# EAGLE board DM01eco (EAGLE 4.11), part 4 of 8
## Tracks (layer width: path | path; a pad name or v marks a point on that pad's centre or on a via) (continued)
DA8-2  (via drill 0.61) (continued)
  Route15 0.152: v267.97,93.98 268.61,93.98 273.05,89.54 v273.05,88.9
DA8-3  (via drill 0.61)
  Top 0.152: v114.94,38.1 117.47,40.64 117.47,52.07 137.16,71.75 139.7,71.75 140.97,73.03 145.41,73.03 v146.05,73.66 | v160.02,62.23 161.93,64.14 161.93,64.77 162.56,65.41 167.64,65.41 185.42,83.19 v185.42,83.82 | v216.53,64.14 217.17,64.14 219.07,66.04 219.07,71.12 241.3,93.34 v245.75,93.34
  Route2 0.152: v245.75,93.34 243.84,95.25 247.65,99.06 247.65,99.7 251.46,103.51 256.54,103.51 259.08,106.05 260.35,106.05 260.99,106.68 262.89,106.68 264.8,104.78 266.06,106.05 273.05,106.05 276.86,109.86 285.75,109.86 291.46,104.14 293.37,104.14 C09.N2
  Route15 0.152: v131.44,15.88 131.44,16.51 117.47,30.48 117.47,35.56 v114.94,38.1 | v185.42,83.82 186.69,83.82 187.96,82.55 198.12,82.55 v216.53,64.14
  Bottom 0.152: v131.44,15.88 128.91,15.88 D22.V2 | v146.05,73.66 149.86,73.66 158.75,64.77 158.75,63.5 v160.02,62.23
DA8-4  (via drill 0.61)
  Top 0.152: v114.3,15.24 102.23,3.18 78.74,3.18 77.47,1.91 75.56,1.91 65.41,12.07 65.41,15.24 D27.V2 | v147.96,1.91 154.31,1.91 154.94,2.54 156.21,2.54 175.26,21.59 175.26,23.5 173.35,25.4 175.26,27.3 v180.97,27.3 | v207.65,2.54 208.28,2.54 222.25,16.51 222.25,17.14 231.14,26.04 231.78,26.04 234.95,29.21 234.95,29.84 v259.71,54.61
  Route2 0.152: v259.71,54.61 259.71,55.88 262.25,58.42 262.89,58.42 276.23,71.75 278.76,71.75 291.46,84.46 291.46,85.73 v297.81,92.08
  Route15 0.152: v114.3,15.24 114.94,14.61 120.02,14.61 121.28,13.34 124.46,13.34 126.36,11.43 128.27,11.43 132.08,7.62 142.24,7.62 v147.96,1.91
  Bottom 0.152: v180.97,27.3 182.25,28.58 207.65,3.18 v207.65,2.54 | v297.81,92.08 295.27,94.62 295.27,96.52 294,97.79 C09.R2
DA8-5  (via drill 0.61)
  Top 0.152: v220.34,116.21 220.34,116.84 226.06,122.56 227.97,122.56 235.59,114.94 v234.95,114.3
  Route2 0.152: v234.95,114.3 236.85,114.3 240.03,111.12 241.3,112.4 243.84,112.4 248.92,107.32 251.46,109.86 259.08,109.86 261.62,107.32 264.16,109.86 272.42,109.86 274.32,107.95 278.76,112.4 v283.85,112.4 | v299.72,100.33 298.45,100.33 296.55,98.43 296.55,97.16 295.27,95.89 295.27,93.98 294,92.71 C09.T2
  Route15 0.152: v220.34,116.21 220.34,116.84 218.44,118.75 213.36,118.75 211.46,120.65 210.82,120.65 196.22,135.25 191.13,135.25 190.5,135.89 189.87,135.89 175.26,150.5 175.26,153.03 151.76,176.53 151.13,176.53 149.86,177.8 149.86,178.44 134.62,193.68 133.99,193.68 132.72,194.94 132.72,195.58 115.57,212.72 115.57,221.62 A23.V2 | v283.85,112.4 283.85,111.76 295.27,100.33 v299.72,100.33
DA8-6  (via drill 0.61)
  Top 0.152: v270.51,118.75 266.7,118.75 v259.08,111.12 | v223.52,125.73 222.88,125.73 221.62,124.46 221.62,121.92 222.88,120.65 218.44,116.21 216.53,116.21 215.9,116.84 215.26,116.21 213.36,116.21 206.38,109.22 v206.38,108.59
  Route2 0.152: v173.99,147.32 170.81,150.5 168.28,147.96 167,147.96 165.1,146.05 161.29,149.86 160.66,149.22 157.48,149.22 156.84,148.59 151.76,148.59 150.5,147.32 149.22,147.32 146.69,144.78 124.46,144.78 119.38,149.86 v118.11,148.59
  Route15 0.152: v270.51,118.75 270.51,118.11 296.55,92.08 294,89.54 294,86.36 C09.V2 | v242.57,126.37 236.22,120.02 234.31,121.92 228.6,121.92 227.97,122.56 227.33,122.56 225.43,124.46 225.43,125.09 224.79,125.73 v223.52,125.73 | v118.11,148.59 116.84,148.59 107.31,158.12 107.31,158.75 100.97,165.1 100.33,165.1 72.39,193.04 71.75,193.04 60.33,204.47 60.33,205.74 54.61,211.46 54.61,212.72 53.98,213.36 53.98,220.34 52.7,221.62 A28.V2
  Bottom 0.152: v259.08,111.12 246.38,123.83 245.11,123.83 v242.57,126.37 | v206.38,108.59 206.38,112.4 199.39,119.38 193.68,119.38 180.97,132.08 180.97,134.62 184.78,138.43 184.15,139.06 184.15,140.34 183.51,140.97 180.34,140.97 v173.99,147.32
DA9  (via drill 0.61)
  Top 0.152: v268.61,233.05 269.24,233.05 276.23,240.03 276.23,240.66 277.5,241.94 278.76,241.94 302.26,265.43 305.44,265.43 306.07,266.06 A08.D2
  Route2 0.152: v268.61,233.05 266.7,231.14 266.7,229.87 250.82,214 250.82,212.72 245.75,207.65 244.47,207.65 234.95,198.12 234.95,197.49 234.31,196.85 234.95,196.22 234.95,193.04 233.04,191.14 228.6,195.58 226.06,195.58 225.43,194.94 219.07,194.94 217.81,193.68 217.81,193.04 215.26,190.5 218.44,187.33 217.81,186.69 217.81,184.78 B15.J2
DA9-0  (via drill 0.61)
  Route2 0.152: v289.56,85.09 295.91,91.44 295.91,92.08 298.45,94.62 298.45,95.89 297.18,97.16 297.81,97.79 v297.81,98.43
  Route15 0.152: v289.56,85.09 292.1,82.55 292.1,76.2 296.55,71.75 298.45,71.75 306.07,64.14 306.07,60.96 D08.D2
  Bottom 0.152: v297.81,98.43 295.27,100.97 295.27,106.05 283.85,117.48 283.21,117.48 281.94,118.75 281.94,122.56 281.31,123.19 C10.F2
DA9-1  (via drill 0.61)
  Top 0.152: v250.82,77.47 250.82,78.11 276.86,104.14 276.86,104.78 278.13,106.05 278.76,106.05 282.57,109.86 v282.57,113.67
  Route2 0.152: v250.82,74.3 247.65,71.12 247.65,69.22 243.21,64.77 243.21,60.96 D13.D2
  Route15 0.152: v250.82,74.3 v250.82,77.47
  Bottom 0.152: v282.57,113.67 282.57,115.57 281.31,116.84 C10.J2
DA9-2  (via drill 0.61)
  Top 0.152: v208.28,29.21 208.91,29.21 v254.63,74.93 | v250.19,79.38 250.19,83.82 257.81,91.44 257.81,92.08 262.25,96.52 262.89,96.52 271.14,104.78 271.78,104.78 276.86,109.86 280.04,109.86 280.67,110.49 C10.L2
  Route15 0.152: v250.19,79.38 v254.63,74.93
  Bottom 0.152: v208.28,29.21 207.65,29.21 196.85,40.01 196.85,40.64 189.23,48.26 188.59,48.26 179.71,57.15 179.71,59.69 D18.D2
DA9-3  (via drill 0.61)
  Top 0.152: v121.28,63.5 118.75,60.96 116.2,60.96 D23.D2 | v189.87,13.34 193.04,13.34 203.2,23.5 208.91,23.5 234.95,49.53 234.95,52.7 v234.31,53.34 | v236.85,58.42 237.49,58.42 247.65,68.58 247.65,69.85 260.35,82.55 261.62,82.55 269.88,90.81 269.88,96.52 276.86,103.51 280.04,103.51 280.67,104.14 C10.N2
  Route2 0.152: v234.31,53.34 234.31,55.88 v236.85,58.42
  Route15 0.152: v121.28,63.5 122.56,63.5 152.4,33.66 153.03,33.66 156.21,30.48 161.93,30.48 165.1,27.3 170.81,27.3 182.25,15.88 182.25,15.24 183.51,13.97 189.23,13.97 v189.87,13.34
DA9-4  (via drill 0.61)
  Route2 0.152: v71.12,78.11 64.14,71.12 64.14,69.22 55.88,60.96 52.7,60.96 D28.D2 | v154.31,10.79 158.12,10.79 174.62,27.3 175.9,27.3 178.44,29.84 184.15,29.84 190.5,36.2 196.22,36.2 200.66,40.64 200.66,41.27 201.93,42.55 206.38,42.55 210.82,38.1 212.72,40.01 219.71,40.01 228.6,48.89 v231.78,48.89 | v241.3,41.91 241.3,43.81 241.94,44.45 241.94,45.72 240.03,47.62 251.46,59.05 256.54,59.05 257.18,59.69 257.18,65.41 282.57,90.81 282.57,94.62 280.04,97.16 280.67,97.79 C10.R2
  Route15 0.152: v133.35,12.07 153.03,12.07 v154.31,10.79
  Bottom 0.152: v71.12,78.11 71.12,76.84 93.98,53.98 93.98,52.7 95.25,51.43 95.25,48.89 93.98,47.62 104.78,36.83 110.49,36.83 127.64,19.69 127.64,17.14 126.36,15.88 129.54,12.7 132.72,12.7 v133.35,12.07 | v231.78,48.89 232.41,48.89 236.22,45.09 236.22,44.45 239.4,41.27 240.66,41.27 v241.3,41.91
DA9-5  (via drill 0.61)
  Top 0.152: v265.43,81.28 267.33,81.28 276.86,90.81 280.04,90.81 280.67,91.44 C10.T2
  Route2 0.152: v175.9,179.07 175.9,177.8 171.45,173.36 171.45,172.09 170.81,171.45 170.81,169.55 172.72,167.64 168.28,163.19 v168.28,153.03 | v219.07,100.97 219.07,99.06 224.16,93.98 224.79,93.98 229.87,88.9 227.97,87 v227.33,87 | v244.47,69.85 244.47,70.48 245.11,71.12 246.38,71.12 250.82,75.57 253.37,75.57 260.35,82.55 261.62,82.55 262.89,83.82 264.16,83.82 266.06,81.92 v265.43,81.28
  Route15 0.152: v175.9,179.07 175.26,179.07 168.28,186.06 168.28,191.77 157.48,202.56 158.75,203.84 158.75,207.01 158.12,207.65 158.12,209.55 149.86,217.81 149.86,222.89 106.68,266.06 103.5,266.06 A24.D2 | v168.28,153.03 168.28,150.5 187.96,130.81 189.23,130.81 196.85,123.19 196.85,122.56 213.36,106.05 218.44,106.05 222.25,102.23 222.25,100.33 220.98,99.06 v219.07,100.97
  Bottom 0.152: v227.33,87 227.33,86.36 243.84,69.85 v244.47,69.85
DA9-6  (via drill 0.61)
  Top 0.152: v223.52,140.34 226.69,137.16 227.33,137.8 227.97,137.8 229.24,139.06 229.24,140.34 228.6,140.97 v248.92,161.29 | v304.17,104.78 306.7,102.23 298.45,93.98 297.81,93.98 294.64,90.81 288.93,90.81 285.75,87.63 283.85,87.63 281.31,85.09 C10.V2
  Route2 0.152: v210.19,180.97 210.19,180.34 v200.66,170.81
  Route15 0.152: v210.19,180.97 203.2,187.96 203.2,189.23 193.68,198.75 193.68,204.47 161.29,236.86 160.66,236.86 154.94,242.57 149.22,242.57 144.78,247.02 144.78,247.65 101.6,290.83 67.31,290.83 43.81,267.33 40.01,267.33 A29.D2 | v248.92,161.29 249.56,161.29 257.18,153.67 257.18,150.5 271.14,136.53 271.14,135.89 272.42,134.62 273.69,134.62 279.4,128.91 280.04,128.91 281.31,127.64 281.31,127 288.93,119.38 288.93,118.11 290.83,116.21 292.1,116.21 303.53,104.78 v304.17,104.78
  Bottom 0.152: v200.66,170.81 198.12,168.28 213.36,153.03 213.36,150.5 v223.52,140.34
DA10  (via drill 0.61)
  Top 0.152: v271.78,223.52 274.95,226.69 275.59,226.69 307.98,259.08 307.98,261.62 309.25,262.89 A08.E2
  Route2 0.152: v271.78,223.52 271.78,222.89 267.33,218.44 267.33,211.46 263.52,207.65 257.81,207.65 252.73,202.56 251.46,202.56 237.49,188.59 231.78,188.59 221.62,178.44 217.81,178.44 B15.L2
DA10-0  (via drill 0.61)
  Top 0.152: v254.63,107.95 259.08,112.4 259.71,112.4 267.33,120.02 267.33,122.56 267.97,123.19 C11.F2
  Bottom 0.152: v254.63,107.95 259.08,103.51 259.71,103.51 305.44,57.78 309.25,57.78 D08.E2
DA10-1  (via drill 0.61)
  Top 0.152: v233.04,73.03 257.81,97.79 257.81,98.43 260.99,101.6 261.62,101.6 269.88,109.86 v269.88,114.94
  Bottom 0.152: v233.04,73.03 245.75,60.32 245.75,57.78 D13.E2 | v269.88,114.94 269.88,115.57 268.61,116.84 C11.J2
DA10-2  (via drill 0.61)
  Top 0.152: v215.9,83.82 214.63,82.55 209.55,82.55 196.85,69.85 196.85,68.58 189.87,61.59 189.23,61.59 187.32,59.69 187.32,59.05 186.06,57.78 182.88,57.78 D18.E2 | v259.08,104.78 264.16,109.86 267.33,109.86 267.97,110.49 C11.L2
  Route2 0.152: v224.79,75.57 229.24,75.57 238.76,85.09 238.76,85.73 240.03,87 240.66,87 251.46,97.79 251.46,98.43 252.73,99.7 254,99.7 v259.08,104.78
  Route15 0.152: v215.9,83.82 216.53,83.82 v224.79,75.57
DA10-3  (via drill 0.61)
  Top 0.152: v158.75,24.13 159.38,24.13 175.26,40.01 181.61,40.01 184.78,43.18 187.32,43.18 189.23,41.27 v190.5,42.55 | v259.08,98.43 264.16,103.51 267.33,103.51 267.97,104.14 C11.N2
  Route2 0.152: v190.5,42.55 196.22,42.55 226.69,73.03 231.78,73.03 233.04,74.3 234.31,74.3 258.44,98.43 v259.08,98.43
  Route15 0.152: v158.75,24.13 156.21,24.13 150.5,29.84 149.22,29.84 122.56,56.52 119.38,56.52 D23.E2
DA10-4  (via drill 0.61)
  Top 0.152: v115.57,2.54 118.11,2.54 v129.54,13.97 | v144.78,1.91 151.13,8.26 151.76,8.26 153.03,6.99 152.4,6.35 154.31,4.45 160.02,10.16 v160.02,10.79
  Route2 0.152: v160.02,10.79 188.59,10.79 190.5,12.7 203.2,12.7 204.47,13.97 206.38,13.97 222.25,29.84 222.25,30.48 253.37,61.59 254.63,61.59 256.54,63.5 256.54,65.41 266.06,74.93 266.06,76.2 266.7,76.84 266.7,88.27 269.88,91.44 269.88,96.52 268.61,97.79 C11.R2
  Bottom 0.152: v115.57,2.54 103.5,14.61 101.6,14.61 69.85,46.35 63.5,46.35 55.88,53.98 55.88,56.52 D28.E2 | v129.54,13.97 132.72,13.97 v144.78,1.91
DA10-5  (via drill 0.61)
  Top 0.152: v122.56,144.78 122.56,149.22 149.22,175.9 149.22,177.16 151.13,179.07 152.4,179.07 v158.75,185.42 | v100.33,259.08 100.33,259.71 102.23,261.62 104.78,261.62 106.05,262.89 A24.E2
  Route2 0.152: v214.63,46.35 215.26,46.35 215.9,46.99 219.71,43.18 221.62,43.18 222.88,44.45 221.62,45.72 221.62,48.26 245.11,71.75 246.38,71.75 259.71,85.09 259.71,86.36 264.8,91.44 267.97,91.44 C11.T2 | v141.6,113.67 141.6,115.57 146.05,120.02 v146.05,120.65
  Route15 0.152: v158.75,185.42 158.75,187.96 154.94,191.77 154.94,193.04 142.88,205.11 142.88,209.55 139.7,212.72 139.7,220.34 100.97,259.08 v100.33,259.08
  Bottom 0.152: v214.63,46.35 214.63,46.99 196.85,64.77 190.5,64.77 165.74,89.54 165.74,90.17 152.4,103.51 151.76,103.51 v141.6,113.67 | v146.05,120.65 146.05,121.29 145.41,121.92 140.34,121.92 130.18,132.08 130.18,137.8 123.19,144.78 v122.56,144.78
DA10-6  (via drill 0.61)
  Top 0.152: v156.84,204.47 156.84,203.84 v154.31,201.3 | v243.21,94.62 245.11,96.52 v248.92,96.52 | v264.16,82.55 265.43,82.55 267.97,85.09 C11.V2
  Route15 0.152: v156.84,204.47 155.57,205.74 155.57,210.82 139.06,227.33 139.06,228.6 137.79,229.87 136.53,229.87 110.49,255.91 105.41,255.91 104.78,256.54 104.78,261.62 87.63,278.76 81.92,278.76 71.75,288.92 46.99,264.16 43.18,264.16 A29.E2 | v154.31,201.3 153.03,200.03 158.75,194.31 158.75,191.14 157.48,189.87 169.54,177.8 169.54,177.16 173.35,173.36 173.99,173.36 179.71,167.64 179.71,167 180.97,165.74 180.97,160.66 190.5,151.13 194.31,151.13 203.84,141.61 203.84,139.7 209.55,133.98 209.55,131.44 208.28,130.18 213.36,125.09 214.63,125.09 215.9,123.83 215.9,121.92 v243.21,94.62
  Bottom 0.152: v248.92,96.52 248.92,95.89 260.99,83.82 262.89,83.82 v264.16,82.55
DA11  (via drill 0.61)
  Top 0.152: v217.17,167 217.17,170.81 B15.N2 | v255.91,188.59 256.54,188.59 267.33,199.39 267.33,201.93 266.06,203.2 282.57,219.71 283.21,219.71 284.48,220.98 284.48,222.89 295.27,233.68 295.27,239.4 304.8,248.92 304.8,250.19 307.98,253.37 307.98,255.27 309.25,256.54 A08.H2
  Route2 0.152: v223.52,160.66 225.43,160.66 227.33,158.75 254,185.42 254,186.69 v255.91,188.59
  Route15 0.152: v217.17,167 217.81,167 223.52,161.29 v223.52,160.66
DA11-0  (via drill 0.61)
  Top 0.152: v259.71,117.48 259.71,115.57 260.99,114.3 259.71,113.03 255.27,113.03 v253.37,111.12 | v298.45,57.15 300.36,57.15 304.17,53.34 v304.8,53.98
  Route15 0.152: v253.37,111.12 253.37,110.49 255.91,107.95 255.91,106.68 257.18,105.41 257.18,104.78 259.08,102.87 259.71,102.87 260.35,102.23 260.35,100.97 257.81,98.43 262.25,93.98 262.89,93.98 269.88,87 269.88,81.28 289.56,61.59 294.64,61.59 298.45,57.78 v298.45,57.15 | v304.8,53.98 304.8,53.34 305.44,52.7 307.98,52.7 309.25,51.43 D08.H2
  Bottom 0.152: v259.71,117.48 255.91,121.29 255.91,123.19 C12.F2
DA11-1  (via drill 0.61)
  Top 0.152: v230.5,69.22 247.65,86.36 247.65,87 251.46,90.81 v252.09,90.81 | v241.94,102.23 243.21,102.23 254.63,113.67 254.63,116.21 255.27,116.84 C12.J2
  Bottom 0.152: v230.5,69.22 245.75,53.98 245.75,51.43 D13.H2 | v252.09,90.81 252.09,92.08 v241.94,102.23
DA11-2  (via drill 0.61)
  Top 0.152: v189.23,46.99 189.23,47.62 201.29,59.69 201.93,59.69 207.01,64.77 212.09,64.77 247.65,100.33 247.65,103.51 246.38,104.78 251.46,109.86 254.63,109.86 255.27,110.49 C12.L2
  Route15 0.152: v189.23,46.99 186.06,50.16 182.88,50.16 D18.H2
DA11-3  (via drill 0.61)
  Top 0.152: v153.67,6.35 175.26,27.94 176.53,27.94 178.44,29.84 184.15,29.84 205.74,51.43 v206.38,51.43 | v227.33,71.75 230.5,71.75 243.21,84.46 243.84,84.46 247.65,88.27 247.65,90.81 246.38,92.08 251.46,97.16 252.73,97.16 254,98.43 254,99.06 256.54,101.6 v257.18,101.6
  Route2 0.152: v114.94,43.81 118.75,47.62 118.75,50.16 D23.H2 | v206.38,51.43 206.38,52.07 226.06,71.75 v227.33,71.75
  Bottom 0.152: v114.94,43.81 115.57,43.81 120.02,39.37 121.28,39.37 130.81,29.84 130.81,29.21 v153.67,6.35 | v257.18,101.6 257.18,102.87 255.91,104.14 C12.N2
DA11-4  (via drill 0.61)
  Top 0.152: v109.86,4.45 110.49,4.45 115.57,9.53 119.38,9.53 152.4,42.55 157.48,42.55 158.75,43.81 v158.75,44.45 | v201.93,3.81 248.28,50.16 248.28,50.8 249.56,52.07 250.19,52.07 254.63,56.52 254.63,58.42 253.37,59.69 v254,60.32
  Route2 0.152: v254,66.04 253.37,66.67 256.54,69.85 256.54,76.84 v257.18,77.47 | v253.37,82.55 254.63,82.55 257.81,85.73 257.81,87.63 253.37,92.08 v257.18,95.89
  Route15 0.152: v176.53,23.5 180.97,23.5 190.5,13.97 191.77,13.97 v201.93,3.81
  Bottom 0.152: v109.86,4.45 103.5,10.79 97.79,10.79 91.44,17.14 86.36,17.14 85.72,17.78 79.38,17.78 55.88,41.27 57.15,42.55 57.15,45.09 55.88,46.35 55.88,50.16 D28.H2 | v158.75,44.45 160.02,44.45 165.74,38.73 165.74,36.2 164.47,34.92 171.45,27.94 171.45,27.3 175.26,23.5 v176.53,23.5 | v254,60.32 254,60.96 256.54,63.5 v254,66.04 | v257.18,77.47 257.18,78.74 v253.37,82.55 | v257.18,95.89 257.18,96.52 255.91,97.79 C12.R2
DA11-5  (via drill 0.61)
  Route2 0.152: v257.81,99.7 260.35,99.7 260.99,100.33 262.89,100.33 264.8,98.43 260.35,93.98 257.18,93.98 255.91,92.71 C12.T2
  Route15 0.152: v229.87,128.27 227.33,130.81 226.69,130.81 210.82,146.69 208.91,146.69 207.01,148.59 207.01,149.86 206.38,150.5 206.38,153.67 193.68,166.37 193.68,179.07 165.74,207.01 165.74,220.34 109.86,276.22 101.6,267.97 101.6,266.06 106.05,261.62 106.05,257.81 A24.H2 | v245.75,111.76 245.75,111.12 257.18,99.7 v257.81,99.7
  Bottom 0.152: v229.87,128.27 229.87,127 238.76,118.11 238.76,117.48 240.03,116.21 241.3,116.21 v245.75,111.76
DA11-6  (via drill 0.61)
  Top 0.152: v233.68,99.7 234.31,99.7 238.76,104.14 238.76,104.78 240.03,106.05 240.66,106.05 241.94,107.32 241.94,108.59 243.21,109.86 245.11,109.86 v247.01,111.76 | v226.06,149.22 224.79,150.5 220.98,150.5 219.71,149.22 218.44,149.22 215.26,152.4 v219.07,156.21 | v81.92,280.03 73.03,280.03 72.39,279.4 67.94,279.4 62.87,274.32 60.96,274.32 59.05,276.22 43.81,260.99 43.81,258.44 43.18,257.81 A29.H2
  Route2 0.152: v248.28,81.92 251.46,85.09 255.27,85.09 C12.V2
  Route15 0.152: v219.07,156.21 217.81,156.21 214,160.02 213.36,160.02 208.91,164.47 208.91,166.37 210.82,168.28 202.56,176.53 200.66,176.53 198.75,174.62 170.81,202.56 170.81,205.11 172.09,206.38 171.45,207.01 171.45,217.81 170.18,219.08 170.18,221.62 161.29,230.5 156.21,230.5 152.4,234.31 v152.4,234.95 | v146.05,244.47 146.05,245.11 139.7,251.46 139.7,252.09 113.67,278.13 88.9,278.13 87.63,279.4 82.55,279.4 v81.92,280.03
  Bottom 0.152: v248.28,81.92 248.28,83.19 235.59,95.89 234.95,95.89 233.68,97.16 v233.68,99.7 | v247.01,111.76 249.56,114.3 246.38,117.48 246.38,118.11 245.11,119.38 243.84,119.38 238.12,125.09 238.12,126.37 237.49,127 237.49,128.27 242.57,133.35 240.66,135.25 238.76,135.25 236.85,133.35 233.04,137.16 234.95,139.06 234.95,140.97 228.6,147.32 227.97,147.32 v226.06,149.22 | v152.4,234.95 151.13,234.95 145.41,240.66 145.41,242.57 146.69,243.84 v146.05,244.47
DA_SEL_DEV0  (via drill 0.61)
  Top 0.152: v214.63,123.83 215.26,123.83 216.53,125.09 219.07,125.09 220.34,126.37 C15.E2 | C13.E2 245.75,126.37 244.47,125.09 241.94,125.09 240.03,123.19 236.85,126.37 233.68,126.37 C14.E2 233.04,126.37 231.78,125.09 229.24,125.09 227.97,123.83 v227.33,123.83 | v366.39,125.09 370.84,125.09 372.75,127 C03.E2 | 297.18,127.64 300.99,127.64 302.26,128.91 307.98,128.91 309.25,127.64 C08.E2 309.88,126.37 313.06,126.37 316.23,123.19 318.13,125.09 320.68,125.09 321.94,126.37 C07.E2 | 297.18,127.64 C09.E2 297.18,127.64 | v344.17,120.02 347.35,123.19 347.35,126.37 C05.E2 | v354.33,123.19 357.5,126.37 360.05,126.37 C04.E2 | 297.18,127.64 298.45,128.91 296.55,130.81 294.64,128.91 289.56,128.91 288.93,128.27 285.75,128.27 285.12,127.64 284.48,127.64 C10.E2 | v401.32,133.98 401.32,132.72 399.42,130.81 399.42,128.27 398.78,127.64 C01.E2 398.14,126.37 396.88,125.09 v390.52,125.09 | v291.46,221.62 293.37,219.71 297.81,224.16 298.45,224.16 v305.44,231.14 | v381,124.46 381.63,125.09 384.18,125.09 385.44,126.37 C02.E2
  Route2 0.152: v227.33,123.83 224.16,127 220.98,127 C15.E2 | C11.E2 271.78,127.64 273.69,127.64 278.13,123.19 280.04,125.09 282.57,125.09 283.85,126.37 C10.E2 | C13.E2 246.38,127.64 250.19,127.64 251.46,128.91 257.18,128.91 258.44,127.64 C12.E2
  Route15 0.152: v246.38,267.33 243.21,267.33 A13.D2 | v323.21,213.36 325.12,213.36 330.83,207.65 330.83,207.01 339.73,198.12 343.54,198.12 344.17,197.49 B05.D2 | v390.52,125.09 389.25,126.37 386.08,126.37 C02.E2
  Bottom 0.152: v214.63,123.83 211.46,127 208.28,127 C16.E2 | C12.E2 259.08,127.64 262.25,127.64 267.97,133.35 271.14,130.18 271.78,130.18 276.86,125.09 279.4,125.09 282.57,128.27 283.85,127 C10.E2 | v366.39,125.09 365.76,125.09 364.49,126.37 360.68,126.37 C04.E2 | C07.E2 322.58,127.64 325.75,127.64 328.93,130.81 330.83,128.91 333.38,128.91 334.64,127.64 C06.E2 335.28,126.37 335.92,125.73 335.92,123.19 341.63,117.48 v344.17,120.02 | v354.33,123.19 351.79,125.73 348.62,125.73 347.98,126.37 C05.E2 | v401.32,133.98 384.81,150.5 387.35,153.03 387.35,156.21 383.54,160.02 378.46,160.02 377.82,160.66 376.56,160.66 370.84,166.37 370.84,167 344.81,193.04 344.81,196.22 B05.D2 | v246.38,267.33 246.38,266.7 v291.46,221.62 | v305.44,231.14 306.7,231.14 314.96,222.89 314.96,221.62 v323.21,213.36 | v381,124.46 378.46,124.46 377.19,125.73 375.92,125.73 375.29,126.37 373.38,126.37 C03.E2
DA_SEL_DEV1  (via drill 0.61)
  Top 0.152: v214.63,117.48 215.26,117.48 216.53,118.75 219.07,118.75 220.34,120.02 C15.H2 | C14.H2 233.68,121.29 237.49,121.29 238.76,122.56 244.47,122.56 245.75,121.29 C13.H2 | v290.83,117.48 293.37,120.02 296.55,120.02 C09.H2 | v367.03,117.48 367.67,117.48 368.94,118.75 371.48,118.75 372.75,120.02 C03.H2 | v331.47,174.62 344.17,187.33 344.17,189.87 B05.F2 | v353.06,149.86 353.06,148.59 334.01,129.54 | 334.01,129.54 326.39,121.92 323.21,121.92 322.58,121.29 C07.H2 321.94,121.29 320.04,119.38 316.87,122.56 314.96,122.56 311.15,118.75 311.15,118.11 310.51,117.48 311.15,116.84 311.15,113.67 309.25,111.76 307.98,113.03 307.98,114.94 309.25,116.21 309.25,120.02 C08.H2 | 334.01,129.54 v333.38,130.18 | v360.05,116.21 360.05,120.02 C04.H2
  Route2 0.152: C12.H2 258.44,121.29 255.27,121.29 252.73,123.83 250.19,121.29 246.38,121.29 C13.H2 | C15.H2 220.98,121.29 224.79,121.29 226.06,122.56 227.97,122.56 231.14,119.38 233.04,121.29 C14.H2 | v379.73,117.48 381,118.75 382.9,118.75 384.18,120.02 385.44,120.02 C02.H2 | C07.H2 322.58,120.02 325.75,120.02 328.93,116.84 330.83,118.75 333.38,118.75 334.64,120.02 C06.H2
  Route15 0.152: v214.63,117.48 214,117.48 211.46,120.02 208.28,120.02 C16.H2 | v387.35,122.56 386.08,121.29 C02.H2 | v259.08,123.83 259.08,121.29 C12.H2
  Bottom 0.152: C09.H2 297.18,120.02 300.99,120.02 302.26,118.75 308.61,118.75 309.88,120.02 C08.H2 | 269.88,127.64 269.88,126.37 271.14,125.09 271.14,121.29 C11.H2 | 269.88,127.64 271.78,129.54 276.86,124.46 279.4,124.46 280.67,125.73 281.31,125.09 281.94,125.09 282.57,124.46 282.57,122.56 283.85,121.29 C10.H2 284.48,120.02 285.12,119.38 288.29,119.38 290.19,117.48 v290.83,117.48 | v387.35,122.56 391.16,118.75 396.88,118.75 398.14,120.02 C01.H2 | v367.03,117.48 364.49,120.02 360.68,120.02 C04.H2 | v379.73,117.48 379.1,117.48 377.19,119.38 374.01,119.38 373.38,120.02 C03.H2 | v353.06,149.86 353.06,153.03 v331.47,174.62 307.98,198.12 302.26,198.12 298.45,201.93 298.45,202.56 278.76,222.25 280.04,223.52 280.04,226.06 275.59,230.5 269.88,230.5 260.35,240.03 260.35,240.66 258.44,242.57 257.81,242.57 243.21,257.18 243.21,259.71 A13.F2 | 347.35,121.92 347.35,123.19 345.44,125.09 339.73,125.09 336.55,128.27 335.28,128.27 v333.38,130.18 | 347.35,121.92 347.35,121.29 C05.H2 | v360.05,116.21 355.6,116.21 351.79,120.02 351.79,120.65 350.52,121.92 347.35,121.92 | v259.08,123.83 265.43,130.18 266.7,128.91 268.61,128.91 269.88,127.64
DA_SEL_DEV2  (via drill 0.61)
  Top 0.152: C14.K2 233.04,114.94 233.04,116.84 229.87,120.02 225.43,115.57 221.62,115.57 220.98,114.94 C15.K2 | 257.81,117.48 259.08,116.21 259.08,114.94 C12.K2 | 257.81,117.48 256.54,118.75 254,118.75 250.19,114.94 246.38,114.94 C13.K2 | v260.35,122.56 260.35,120.02 257.81,117.48 | v371.48,112.4 372.75,113.67 C03.K2 | v394.97,113.03 396.24,113.03 396.88,112.4 398.14,113.67 C01.K2 | v379.73,109.86 379.73,110.49 381.63,112.4 384.18,112.4 385.44,113.67 C02.K2 | 311.15,121.29 311.15,120.02 309.88,118.75 309.88,114.94 C08.K2 | 311.15,121.29 308.61,123.83 307.34,122.56 302.26,122.56 297.81,118.11 297.81,115.57 297.18,114.94 C09.K2 | v329.56,110.49 329.56,111.12 330.83,112.4 333.38,112.4 334.64,113.67 C06.K2 | v366.39,160.02 366.39,158.75 358.77,151.13 356.24,151.13 323.21,118.11 323.21,115.57 322.58,114.94 C07.K2 | v262.25,269.88 252.09,259.71 251.46,259.71 246.38,254.64 243.21,254.64 A13.J2 | 311.15,121.29 311.79,121.29 v312.42,121.92 | v351.15,109.22 351.79,109.22 356.24,113.67 360.05,113.67 C04.K2
  Route2 0.152: C16.K2 208.28,114.94 208.28,117.48 210.19,119.38 212.72,119.38 214,118.11 214.63,118.75 219.07,118.75 221.62,116.21 220.34,114.94 C15.K2 | C09.K2 296.55,114.94 295.27,116.21 289.56,116.21 288.29,114.94 284.48,114.94 C10.K2 283.85,114.94 282.57,116.21 276.86,116.21 275.59,114.94 271.78,114.94 C11.K2
  Route15 0.152: C14.K2 233.68,114.94 233.68,118.11 235.59,120.02 236.22,119.38 238.12,119.38 238.76,118.75 240.03,118.75 241.3,117.48 241.3,116.84 241.94,116.21 244.47,116.21 245.75,114.94 C13.K2 | C06.K2 335.28,113.67 335.92,113.03 339.09,113.03 341.63,110.49 344.81,113.67 347.35,113.67 C05.K2 347.98,113.67 347.98,109.86 349.88,107.95 v351.15,109.22
  Bottom 0.152: v260.35,122.56 269.24,113.67 271.14,113.67 C11.K2 | v371.48,112.4 365.76,112.4 363.86,114.3 363.22,113.67 360.68,113.67 C04.K2 | v394.97,113.03 393.06,111.12 391.8,111.12 389.25,113.67 386.08,113.67 C02.K2 | v379.73,109.86 379.1,110.49 377.82,109.22 375.29,109.22 373.38,111.12 373.38,113.67 C03.K2 | v329.56,110.49 327.02,113.03 323.85,113.03 323.21,113.67 322.58,113.67 C07.K2 321.94,114.94 320.68,116.21 317.5,116.21 312.42,121.29 v312.42,121.92 | 344.81,182.25 344.81,181.61 349.25,177.16 349.25,176.53 365.76,160.02 v366.39,160.02 | 344.81,182.25 344.81,183.52 B05.J2 | v262.25,269.88 295.27,236.86 301.62,236.86 316.87,221.62 316.87,220.98 333.38,204.47 333.38,198.75 347.35,184.78 347.98,184.78 349.25,183.52 347.98,182.25 344.81,182.25
DA_SEL_DEV3  (via drill 0.61)
  Top 0.152: v228.6,104.78 228.6,105.41 230.5,107.32 233.04,107.32 C14.M2 | v240.03,104.78 242.57,107.32 245.75,107.32 C13.M2 | v278.13,104.78 278.76,104.78 280.04,106.05 282.57,106.05 | 282.57,106.05 283.85,107.32 C10.M2 | 293.37,113.67 296.55,110.49 296.55,108.59 C09.M2 | 293.37,113.67 282.57,102.87 282.57,101.6 280.67,99.7 279.4,100.97 282.57,104.14 282.57,106.05 | v379.73,104.14 381.63,106.05 384.18,106.05 385.44,107.32 C02.M2 | v388.62,106.68 389.25,107.32 390.52,106.05 393.06,106.05 394.33,107.32 398.14,107.32 C01.M2 | v325.12,109.22 324.49,109.22 322.58,107.32 C07.M2 | v371.48,147.96 371.48,141.61 v350.52,120.65 v343.54,113.67 339.09,109.22 335.92,109.22 335.28,108.59 C06.M2 | v252.09,254 250.19,252.09 245.11,252.09 243.21,250.19 243.21,248.28 A13.L2 | 293.37,113.67 293.37,114.94 296.55,118.11 v296.55,118.75 | v261.62,109.22 260.99,108.59 259.08,108.59 C12.M2
  Route2 0.152: C13.M2 246.38,107.32 246.38,104.14 248.92,101.6 251.46,104.14 252.73,104.14 254.63,106.05 257.18,106.05 258.44,107.32 C12.M2 | v210.82,115.57 210.82,114.94 207.65,111.76 207.65,108.59 C16.M2 | C08.M2 309.88,108.59 313.06,108.59 314.96,110.49 316.23,110.49 318.13,112.4 320.04,112.4 323.21,109.22 322.58,108.59 C07.M2 | v367.03,103.51 367.03,104.14 370.2,107.32 372.75,107.32 C03.M2 | v261.62,109.22 262.89,109.22 264.16,110.49 265.43,110.49 v266.06,111.12
  Route15 0.152: v210.82,115.57 210.82,114.94 213.36,112.4 218.44,112.4 219.07,111.76 219.07,109.86 220.34,108.59 C15.M2 | v240.03,104.78 239.4,104.78 237.49,106.68 234.31,106.68 233.68,107.32 C14.M2
  Bottom 0.152: v228.6,104.78 227.33,104.78 224.79,107.32 220.98,107.32 C15.M2 | v278.13,104.78 275.59,107.32 271.78,107.32 C11.M2 271.14,108.59 269.88,109.86 267.33,109.86 v266.06,111.12 | v379.73,104.14 376.56,107.32 373.38,107.32 C03.M2 | v388.62,106.68 386.71,106.68 386.08,107.32 C02.M2 | v325.12,109.22 325.12,108.59 327.66,106.05 328.93,106.05 329.56,105.41 331.47,107.32 334.64,107.32 C06.M2 | 344.81,174.62 344.81,177.16 B05.L2 | v371.48,147.96 344.81,174.62 | v343.54,113.67 344.17,113.67 347.35,110.49 347.35,108.59 C05.M2 | 360.05,111.12 360.05,108.59 C04.M2 | v350.52,120.65 360.05,111.12 | v252.09,254 252.73,254 266.06,240.66 266.7,240.66 273.05,234.31 273.05,233.68 286.38,220.34 290.83,220.34 293.37,217.81 297.18,221.62 314.32,204.47 320.04,204.47 320.68,203.84 320.68,201.3 319.4,200.03 344.81,174.62 | v367.03,103.51 367.03,104.14 360.05,111.12 | v296.55,118.75 296.55,118.11 306.07,108.59 309.25,108.59 C08.M2
DA_SEL_DEV4  (via drill 0.61)
  Top 0.152: v231.78,247.02 232.41,247.02 250.82,265.43 v254,265.43 | v328.93,104.78 325.75,101.6 322.58,101.6 C07.P2 321.94,100.97 321.94,99.06 v320.68,97.79 | v387.99,100.33 391.16,103.51 396.88,103.51 398.14,102.23 C01.P2 | v354.33,98.43 355.6,99.7 358.77,99.7 360.05,100.97 C04.P2 | 369.57,100.97 372.75,100.97 C03.P2 | v367.03,98.43 369.57,100.97 | v379.1,106.05 378.46,106.05 376.56,107.95 369.57,100.97 | C06.P2 335.28,102.23 335.28,104.78 342.9,112.4 343.54,112.4 346.71,115.57 v350.52,115.57 351.79,115.57 355.6,119.38 355.6,120.02 362.58,127 361.31,128.27 361.31,130.81 370.2,139.7 v370.84,139.7 | v214.63,98.43 215.26,98.43 216.53,99.7 219.07,99.7 220.34,100.97 C15.P2 | v231.78,93.98 234.95,93.98 241.94,100.97 245.75,100.97 C13.P2 | v274.32,102.87 272.42,102.87 271.78,102.23 C11.P2 | v287.02,93.98 287.02,94.62 292.1,99.7 295.27,99.7 296.55,100.97 C09.P2 | v241.3,104.78 241.3,105.41 241.94,106.05 246.38,106.05 248.92,108.59 v248.92,109.22
  Route2 0.152: v343.54,205.74 343.54,205.11 339.73,201.3 339.73,200.66 337.82,198.75 337.19,198.75 333.38,194.94 v333.38,184.15 | v387.99,100.33 387.35,99.7 386.08,100.97 C02.P2 | C12.P2 259.08,101.6 262.25,101.6 264.16,103.51 269.88,103.51 271.14,102.23 C11.P2 | v241.3,104.78 240.03,103.51 238.76,103.51 237.49,102.23 233.68,102.23 C14.P2 | v320.68,97.79 320.04,97.16 316.87,97.16 313.06,100.97 v312.42,100.33
  Route15 0.152: v254,265.43 260.35,265.43 264.16,261.62 269.88,261.62 300.36,231.14 300.99,231.14 302.26,229.87 311.15,229.87 313.06,231.78 314.96,229.87 320.68,229.87 343.54,207.01 v343.54,205.74 | v333.38,184.15 333.38,179.71 340.36,172.72 343.54,172.72 344.17,172.09 B05.N2 344.81,170.81 344.81,167.64 360.05,152.4 360.05,151.13 370.84,140.34 v370.84,139.7 | v379.1,106.05 382.9,102.23 385.44,102.23 C02.P2 | v214.63,98.43 214,98.43 211.46,100.97 208.28,100.97 C16.P2
  Bottom 0.152: v231.78,247.02 233.04,245.75 234.31,245.75 236.85,243.21 237.49,243.21 238.76,241.94 242.57,241.94 A13.N2 | v328.93,104.78 329.56,104.78 330.83,103.51 333.38,103.51 334.64,102.23 C06.P2 | v354.33,98.43 351.79,100.97 347.98,100.97 C05.P2 | C04.P2 360.68,100.97 361.31,100.33 364.49,100.33 366.39,98.43 v367.03,98.43 350.52,114.94 v350.52,115.57 | 223.52,100.97 222.88,100.33 220.98,102.23 C15.P2 | 223.52,100.97 226.06,103.51 227.97,103.51 229.24,102.23 233.04,102.23 C14.P2 | v231.78,93.98 228.6,97.16 227.97,97.16 224.16,100.97 223.52,100.97 | 274.95,102.23 276.23,103.51 278.76,103.51 280.04,102.23 283.85,102.23 C10.P2 | 274.95,102.23 v274.32,102.87 | C09.P2 296.55,102.23 296.55,106.05 295.27,107.32 295.27,113.03 294,114.3 296.55,116.84 298.45,114.94 298.45,112.4 297.18,111.12 302.26,106.05 307.34,106.05 307.98,105.41 307.98,103.51 309.25,102.23 C08.P2 309.88,100.97 310.51,100.33 v312.42,100.33 | 274.95,102.23 274.95,101.6 282.57,93.98 v287.02,93.98 | v248.92,109.22 248.92,108.59 257.18,100.33 258.44,101.6 C12.P2
DA_SEL_DEV5  (via drill 0.61)
  Top 0.152: v337.82,96.52 337.19,95.89 335.28,95.89 C06.S2 | v379.1,99.7 378.46,99.06 377.19,100.33 375.29,100.33 373.38,98.43 373.38,95.89 C03.S2 | v234.95,97.16 233.68,95.89 C14.S2 | v204.47,199.39 204.47,200.03 207.65,203.2 208.28,203.2 239.4,234.31 242.57,234.31 A13.R2 | v279.4,98.43 277.5,98.43 275.59,96.52 272.42,96.52 271.78,95.89 C11.S2 | v290.83,92.08 293.37,94.62 296.55,94.62 C09.S2 297.18,95.89 v298.45,97.16 | v285.75,97.16 284.48,95.89 C10.S2 | v303.53,92.71 307.98,97.16 309.25,95.89 C08.S2
  Route2 0.152: v354.96,92.08 356.87,93.98 358.77,93.98 359.41,94.62 360.05,94.62 C04.S2 | C08.S2 309.88,94.62 313.06,94.62 316.23,91.44 318.13,93.34 320.68,93.34 321.94,94.62 C07.S2 322.58,95.89 323.85,97.16 320.68,100.33 320.68,102.23 322.58,104.14 | v357.5,149.22 357.5,147.32 v354.96,144.78 347.35,137.16 347.35,135.25 346.07,133.98 346.07,128.91 323.85,106.68 323.85,105.41 322.58,104.14 | 322.58,104.14 v323.21,104.14 | C15.S2 220.34,94.62 219.07,93.34 216.53,93.34 214.63,91.44 211.46,94.62 208.28,94.62 C16.S2 208.28,95.89 208.91,96.52 208.91,99.06 213.36,103.51 218.44,103.51 220.34,105.41 229.87,95.89 233.04,95.89 C14.S2 | v271.14,83.82 271.14,87 268.61,89.54 270.51,91.44 270.51,93.98 271.14,94.62 C11.S2 | v285.75,97.16 v290.83,92.08 | v246.38,90.81 246.38,92.08 v252.73,98.43
  Route15 0.152: C01.S2 398.14,94.62 394.33,94.62 391.8,92.08 389.89,93.98 386.71,93.98 386.08,94.62 C02.S2 385.44,95.89 384.18,97.16 381.63,97.16 v379.1,99.7 378.46,99.7 376.56,101.6 376.56,102.23 379.1,104.78 374.65,109.22 374.65,110.49 374.01,111.12 374.01,113.03 375.29,114.3 368.3,121.29 368.3,121.92 361.95,128.27 361.95,129.54 358.77,132.72 358.77,137.8 359.41,138.43 358.77,139.06 358.77,140.97 v354.96,144.78 | v234.95,97.16 238.76,93.34 244.47,93.34 245.75,94.62 C13.S2 | v204.47,199.39 206.38,197.49 206.38,186.06 216.53,175.9 217.17,175.9 218.44,174.62 218.44,173.36 238.76,153.03 238.76,151.77 244.47,146.05 244.47,144.15 257.18,131.44 257.18,118.75 273.05,102.87 273.05,99.06 270.51,96.52 271.14,95.89 C11.S2 | v303.53,92.71 302.89,92.71 v298.45,97.16
  Bottom 0.152: v337.82,96.52 337.82,95.89 342.9,90.81 345.44,90.81 347.35,92.71 344.81,95.25 344.81,95.89 342.9,97.79 342.9,99.7 344.17,100.97 346.07,99.06 346.07,97.16 347.35,95.89 C05.S2 347.98,94.62 348.62,93.98 351.79,93.98 353.69,92.08 v354.96,92.08 | v357.5,149.22 347.98,158.75 349.25,160.02 349.25,162.56 347.35,164.47 344.81,164.47 B05.R2 | v323.21,104.14 331.47,95.89 334.64,95.89 C06.S2 | 259.08,92.71 259.08,92.08 264.16,87 269.24,87 269.88,86.36 269.88,85.09 v271.14,83.82 | 259.08,92.71 259.08,94.62 C12.S2 | v279.4,98.43 279.4,97.79 282.57,94.62 283.85,94.62 C10.S2 | v246.38,90.81 246.38,91.44 244.47,93.34 245.75,94.62 C13.S2 | v252.73,98.43 253.37,98.43 259.08,92.71
DA_SEL_DEV6  (via drill 0.61)
  Top 0.152: v214.63,85.09 216.53,87 219.07,87 220.34,88.27 C15.U2 220.34,89.54 220.34,92.71 223.52,95.89 v223.52,96.52 | v240.03,85.73 240.66,85.73 241.94,87 244.47,87 245.75,88.27 C13.U2 | v254,86.36 255.91,88.27 258.44,88.27 C12.U2 | v262.89,82.55 268.61,88.27 271.14,88.27 C11.U2 | v276.23,83.19 281.31,88.27 283.85,88.27 C10.U2 | v285.12,76.84 292.74,84.46 294.64,84.46 296.55,86.36 296.55,88.27 C09.U2 | v379.73,85.73 384.18,90.17 384.81,89.54 385.44,89.54 C02.U2 | v316.23,85.73 316.87,85.73 318.13,87 | 318.13,87 320.68,87 321.94,88.27 C07.U2 | v328.93,85.73 331.47,88.27 334.64,88.27 C06.U2 | 338.45,155.58 335.92,153.03 335.92,148.59 333.38,146.05 333.38,142.88 332.11,141.61 332.11,140.34 319.4,127.64 v318.77,127.64 | 338.45,155.58 341,158.12 344.17,158.12 B05.T2 | v336.55,107.95 336.55,106.68 323.85,93.98 323.85,92.71 318.13,87 | v258.44,241.3 246.38,229.24 243.21,229.24 A13.T2 | 338.45,155.58 v337.82,155.58 | v341.63,85.73 344.17,88.27 347.35,88.27 C05.U2 | v303.53,85.73 304.17,85.73 305.44,87 307.98,87 309.25,88.27 C08.U2
  Route2 0.152: C04.U2 360.68,88.27 364.49,88.27 369.57,83.19 371.48,85.09 371.48,87 372.75,88.27 C03.U2 373.38,89.54 374.65,90.81 v379.73,85.73
  Route15 0.152: v214.63,85.09 211.46,88.27 208.28,88.27 C16.U2 | C01.U2 398.14,89.54 397.51,89.54 396.88,90.17 392.43,85.73 387.35,90.81 387.35,91.44 386.71,92.08 386.71,92.71 385.44,93.98 384.18,92.71 384.18,90.81 385.44,89.54 C02.U2 | C04.U2 360.05,88.27 358.77,87 358.77,85.09 353.69,80.01 348.62,85.09 348.62,87.63 347.98,88.27 C05.U2 | v303.53,85.73 300.99,88.27 297.18,88.27 C09.U2
  Bottom 0.152: v240.03,85.73 237.49,88.27 233.68,88.27 C14.U2 233.04,89.54 231.78,90.81 228.6,90.81 223.52,95.89 v223.52,96.52 | 252.73,86.36 252.09,86.36 249.56,88.9 246.38,88.9 C13.U2 | 252.73,86.36 v254,86.36 | v262.89,82.55 256.54,82.55 252.73,86.36 | C11.U2 271.78,88.27 272.42,87.63 272.42,85.09 274.32,83.19 v276.23,83.19 282.57,76.84 v285.12,76.84 | v316.23,85.73 313.69,88.27 309.88,88.27 C08.U2 | v328.93,85.73 328.3,85.73 326.39,87.63 323.21,87.63 322.58,88.27 C07.U2 | v318.77,127.64 318.77,127 336.55,109.22 v336.55,107.95 | v258.44,241.3 273.69,226.06 273.69,225.43 274.95,224.16 275.59,224.16 295.27,204.47 295.27,198.12 v337.82,155.58 | v341.63,85.73 341,85.73 339.09,87.63 335.92,87.63 335.28,88.27 C06.U2
DAEX1  (via drill 0.61)
  Top 0.152: v145.41,228.6 145.41,229.24 155.57,239.4 161.93,239.4 187.96,265.43 193.68,265.43 v219.07,290.83
  Route2 0.152: v145.41,228.6 144.15,227.33 142.88,227.33 125.09,209.55 123.83,209.55 122.56,208.28 111.12,208.28 97.79,194.94 97.16,194.94 93.34,191.14 90.81,191.14 B25.F2
  Bottom 0.152: v219.07,290.83 222.88,290.83 224.16,289.56 243.21,289.56 257.81,274.95 262.89,274.95 267.33,270.51 267.33,267.97 267.97,267.33 A11.D2
DAEX1-0  (via drill 0.61)
  Top 0.152: v260.99,55.88 264.16,59.05 264.8,59.05 265.43,59.69 267.97,59.69 D11.D2
  Bottom 0.152: v260.99,55.88 257.18,55.88 219.07,93.98 219.07,99.06 218.44,99.7 213.36,99.7 212.09,100.97 212.09,102.23 214,104.14 214.63,103.51 215.9,104.78 215.9,106.68 217.17,107.95 209.55,115.57 209.55,116.84 206.38,120.02 206.38,121.92 205.1,123.19 C16.F2
DAEX1-1  (via drill 0.61)
  Top 0.152: v175.9,87 175.26,87 173.35,88.9 v182.25,97.79
  Route2 0.152: v182.25,97.79 182.25,98.43 197.49,113.67 198.12,113.67 200.66,116.21 203.84,116.21 204.47,116.84 C16.J2
  Bottom 0.152: v175.9,87 186.06,76.84 187.96,76.84 193.68,71.12 196.85,71.12 204.47,63.5 204.47,60.96 D16.D2
DAEX1-2  (via drill 0.61)
  Top 0.152: v198.12,106.68 198.12,107.32 200.66,109.86 203.84,109.86 204.47,110.49 C16.L2
  Route2 0.152: v140.34,64.14 140.97,64.14 147.96,71.12 147.96,72.39 154.31,78.74 154.31,80.65 155.57,81.92 158.75,81.92 159.38,82.55 166.37,82.55 180.97,97.16 180.97,103.51 v191.13,113.67
  Route15 0.152: v191.13,113.67 191.77,113.67 198.12,107.32 v198.12,106.68
  Bottom 0.152: v140.34,64.14 140.97,63.5 140.97,60.96 D21.D2
DAEX1-3  (via drill 0.61)
  Top 0.152: v117.47,95.25 115.57,93.34 114.3,93.34 98.42,77.47 98.42,76.2 93.34,71.12 92.08,71.12 85.72,64.77 80.01,64.77 78.11,62.87 78.11,60.96 D26.D2 | v127.64,102.23 128.27,102.23 133.35,107.32 133.35,109.86 132.08,111.12 143.51,122.56 143.51,123.83 v146.05,126.37 | v171.45,113.03 174.62,113.03 176.53,111.12 178.44,113.03 184.15,113.03 187.96,116.84 189.87,116.84 v190.5,117.48
  Route2 0.152: v117.47,95.25 117.47,95.89 118.11,96.52 123.19,96.52 127.64,100.97 v127.64,102.23
  Route15 0.152: v190.5,117.48 189.87,116.84 200.66,106.05 203.84,106.05 204.47,105.41 C16.N2
  Bottom 0.152: v146.05,126.37 147.96,126.37 153.67,120.65 154.94,120.65 156.21,119.38 161.93,119.38 168.28,113.03 v171.45,113.03
DAEX1-4  (via drill 0.61)
  Top 0.152: v78.74,1.27 104.78,1.27 131.44,27.94 132.08,27.94 133.35,29.21 133.35,29.84 v149.86,46.35
  Route2 0.152: v149.86,46.35 165.1,61.59 165.74,61.59 171.45,67.31 171.45,67.95 175.26,71.75 180.34,71.75 184.15,75.57 185.42,75.57 203.2,93.34 204.47,93.34 v206.38,95.25
  Bottom 0.152: v78.74,1.27 66.04,13.97 57.15,13.97 14.61,56.52 14.61,59.69 D31.D2 | v206.38,95.25 206.38,96.52 205.1,97.79 C16.R2
DAEX1-5  (via drill 0.61)
  Top 0.152: v63.5,170.81 63.5,172.09 68.58,177.16 68.58,178.44 90.17,200.03 91.44,200.03 92.71,201.3 97.79,201.3 99.06,202.56 99.06,203.84 97.16,205.74 97.79,206.38 97.79,210.19 v100.97,213.36
  Route2 0.152: v172.09,62.23 180.97,71.12 184.78,71.12 189.23,75.57 188.59,76.2 188.59,78.11 194.31,83.82 199.39,83.82 204.47,88.9 204.47,91.44 C16.T2
  Route15 0.152: v131.44,109.86 131.44,111.12 110.49,132.08 104.78,132.08 89.53,147.32 86.36,147.32 63.5,170.18 v63.5,170.81 | v100.97,213.36 100.97,215.27 92.08,224.16 92.08,229.87 82.55,239.4 82.55,240.66 79.38,243.84 79.38,249.56 66.67,262.25 66.67,264.8 65.41,266.06 A27.D2
  Bottom 0.152: v172.09,62.23 168.28,62.23 154.94,75.57 154.31,75.57 139.7,90.17 139.7,90.81 130.18,100.33 130.18,102.87 132.08,104.78 130.18,106.68 130.18,108.59 v131.44,109.86
DAEX1-6  (via drill 0.61)
  Route2 0.152: v147.32,119.38 148.59,119.38 168.28,99.7 168.28,97.16 v167,95.89
  Route15 0.152: v51.44,201.3 53.34,199.39 53.34,198.75 66.67,185.42 66.67,179.71 80.64,165.74 81.28,165.74 82.55,164.47 82.55,163.83 92.08,154.31 97.79,154.31 102.87,149.22 104.78,149.22 105.41,148.59 107.95,148.59 118.11,138.43 123.19,138.43 135.25,126.37 135.89,126.37 142.88,119.38 v147.32,119.38 | v167,95.89 167,95.25 172.09,90.17 174.62,90.17 176.53,92.08 177.8,90.81 182.88,90.81 184.15,89.54 185.42,89.54 187.96,87 189.87,87 194.94,92.08 201.29,85.73 204.47,85.73 C16.V2
  Bottom 0.152: v51.44,201.3 43.18,209.55 41.27,209.55 35.56,215.27 35.56,222.89 15.88,242.57 15.88,248.92 1.91,262.89 1.91,266.06 A32.D2
DAEX2  (via drill 0.61)
  Top 0.152: v88.9,207.65 88.9,215.9 92.08,219.08 103.5,219.08 129.54,245.11 129.54,245.75 158.75,274.95 v158.75,276.22
  Route2 0.152: v193.68,247.65 195.58,247.65 215.9,267.97 220.34,267.97 220.98,268.6 222.88,268.6 228.6,274.32 234.95,274.32 238.76,278.13 241.94,278.13 v250.19,286.38
  Route15 0.152: v88.9,207.65 90.17,206.38 88.9,205.11 88.9,202.56 90.17,201.3 90.17,197.49 B25.D2 | v158.75,276.22 160.66,276.22 187.96,248.92 193.04,248.92 193.68,248.28 v193.68,247.65
  Bottom 0.152: v250.19,286.38 252.09,286.38 267.97,270.51 267.97,269.24 269.88,267.33 269.88,265.43 271.14,264.16 A11.E2
DAEX2-0
  Bottom 0.152: D11.E2 271.14,57.78 271.14,60.96 237.49,94.62 237.49,95.89 239.4,97.79 238.12,99.06 238.12,99.7 222.25,115.57 222.25,116.84 219.07,120.02 219.07,121.92 217.81,123.19 C15.F2
DAEX2-1  (via drill 0.61)
  Top 0.152: v191.77,83.82 193.04,83.82 213.36,104.14 213.36,104.78 214.63,106.05 215.26,106.05 v217.81,108.59
  Route2 0.152: v211.46,63.5 208.28,60.32 208.28,57.78 D16.E2
  Bottom 0.152: v211.46,63.5 206.38,68.58 206.38,73.66 196.22,83.82 v191.77,83.82 | v217.81,108.59 220.34,111.12 220.34,112.4 219.07,113.67 219.07,115.57 217.81,116.84 C15.J2
DAEX2-2  (via drill 0.61)
  Route2 0.152: v169.54,81.92 166.37,78.74 166.37,76.84 154.94,65.41 154.94,64.77 147.96,57.78 144.78,57.78 D21.E2 | v179.71,74.3 182.25,74.3 186.06,78.11 187.32,78.11 213.36,104.14 213.36,104.78 214.63,106.05 215.26,106.05 216.53,107.32 216.53,109.86 217.17,110.49 C15.L2
  Bottom 0.152: v169.54,81.92 174.62,76.84 177.16,76.84 v179.71,74.3
DAEX2-3  (via drill 0.61)
  Top 0.152: v201.29,87 202.56,87 213.36,97.79 213.36,98.43 214.63,99.7 215.9,99.7 v218.44,102.23
  Route2 0.152: v107.95,38.73 110.49,38.73 111.76,40.01 117.47,40.01 v149.86,72.39 | v160.02,63.5 165.74,69.22 165.74,72.39 177.16,83.82 179.71,83.82 184.78,88.9 186.06,88.9 190.5,93.34 192.41,93.34 v193.68,94.62
  Route15 0.152: v107.95,38.73 104.14,42.55 99.06,42.55 85.09,56.52 81.28,56.52 D26.E2 | v149.86,72.39 150.5,73.03 v160.02,63.5
  Bottom 0.152: v193.68,94.62 193.68,93.98 200.66,87 v201.29,87 | v218.44,102.23 218.44,103.51 217.81,104.14 C15.N2
DAEX2-4  (via drill 0.61)
  Top 0.152: v148.59,141.61 149.22,141.61 v158.75,151.13
  Route2 0.152: v148.59,141.61 147.32,142.88 138.43,142.88 134.62,139.06 133.35,139.06 132.08,137.8 127.64,137.8 125.73,135.89 124.46,135.89 117.47,128.91 111.76,128.91 109.86,127 107.95,128.91 99.06,128.91 98.42,128.27 92.08,128.27 55.88,92.08 57.15,90.81 57.15,87.63 47.62,78.11 47.62,76.2 42.55,71.12 41.27,71.12 29.21,59.05 22.86,59.05 21.59,57.78 17.78,57.78 D31.E2
  Route15 0.152: v158.75,151.13 159.38,150.5 160.66,150.5 165.1,146.05 166.37,146.05 210.82,101.6 211.46,101.6 213.36,99.7 216.53,99.7 217.17,99.06 C15.R2
DAEX2-5  (via drill 0.61)
  Top 0.152: v125.09,176.53 v130.18,181.61
  Route2 0.152: v208.28,83.82 207.01,85.09 212.72,90.81 216.53,90.81 217.17,91.44 C15.T2
  Route15 0.152: v130.18,181.61 130.18,185.42 117.47,198.12 117.47,203.84 114.3,207.01 114.3,215.9 111.76,218.44 111.76,222.89 71.75,262.89 68.58,262.89 A27.E2 | v125.09,176.53 124.46,176.53 122.56,174.62 137.16,160.02 142.88,160.02 149.86,153.03 149.86,151.13 158.12,142.88 158.12,140.97 158.75,140.34 158.75,139.7 160.02,138.43 161.29,138.43 171.45,128.27 171.45,126.37 v170.18,125.09 | v180.97,107.95 180.97,106.05 187.32,99.7 193.04,99.7 193.68,99.06 v193.68,98.43
  Bottom 0.152: v170.18,125.09 170.18,123.83 177.8,116.21 177.8,114.94 180.97,111.76 v180.97,107.95 | v193.68,98.43 194.94,98.43 206.38,87 206.38,85.73 v208.28,83.82
DAEX2-6  (via drill 0.61)
  Top 0.152: v150.5,214 153.67,214 158.12,209.55 152.4,203.84 152.4,201.3 154.31,199.39 152.4,197.49 v152.4,196.85
  Route2 0.152: v152.4,196.85 151.13,196.85 142.88,188.59 142.88,182.25 135.89,175.26 135.89,173.36 137.16,172.09 v137.79,172.72
  Route15 0.152: v185.42,106.68 186.69,106.68 196.22,97.16 196.85,97.16 200.66,93.34 207.01,93.34 213.36,87 216.53,87 217.17,86.36 C15.V2
  Bottom 0.152: v150.5,214 150.5,214.63 144.15,220.98 140.34,220.98 138.43,222.89 137.16,222.89 117.47,242.57 117.47,248.28 116.84,248.92 116.84,249.56 93.98,272.41 89.53,267.97 86.36,267.97 63.5,290.83 7.62,290.83 3.17,286.38 3.17,269.24 4.45,267.97 4.45,264.16 A32.E2 | v137.79,172.72 146.05,164.47 146.05,163.83 154.31,155.58 154.31,154.31 155.57,153.03 155.57,150.5 168.28,137.8 168.28,128.91 163.83,124.46 167.64,120.65 167.64,120.02 180.97,106.68 v185.42,106.68
DAEX3  (via drill 0.61)
  Route2 0.152: v203.2,179.71 203.2,180.34 206.38,183.52 206.38,189.23 224.16,207.01 224.16,207.65 236.85,220.34 237.49,220.34 254.63,237.49 255.91,237.49 259.71,241.3 259.71,242.57 269.88,252.73 269.88,255.27 271.14,256.54 A11.H2
  Bottom 0.152: v203.2,179.71 203.2,177.16 205.74,174.62 205.74,173.36 210.82,168.28 208.91,166.37 208.91,164.47 214,159.39 217.17,159.39 B15.T2
DAEX3-0  (via drill 0.61)
  Top 0.152: v262.89,63.5 262.89,64.77 267.33,69.22 267.33,70.48 v277.5,80.65 | v245.11,118.11 242.57,120.65 240.66,118.75 238.12,118.75 236.22,120.65 234.95,119.38 232.41,119.38 229.24,122.56 229.87,123.19 C14.F2
  Route15 0.152: v277.5,80.65 277.5,85.73 259.71,103.51 259.08,103.51 257.81,104.78 257.81,106.68 257.18,107.32 257.18,111.76 256.54,112.4 250.82,112.4 v245.11,118.11
  Bottom 0.152: v262.89,63.5 262.89,62.87 267.33,58.42 267.33,57.15 271.14,53.34 271.14,51.43 D11.H2
DAEX3-1  (via drill 0.61)
  Top 0.152: v236.85,81.92 236.22,81.92 208.28,53.98 208.28,51.43 D16.H2 | v216.53,101.6 224.16,109.22 224.79,109.22 229.24,113.67 229.24,116.21 229.87,116.84 C14.J2
  Bottom 0.152: v236.85,81.92 217.17,101.6 v216.53,101.6
DAEX3-2  (via drill 0.61)
  Top 0.152: v151.76,40.01 155.57,40.01 181.61,66.04 181.61,66.67 v184.15,69.22 | v203.84,83.19 204.47,83.19 211.46,90.17 212.09,90.17 229.24,107.32 229.24,109.86 229.87,110.49 C14.L2
  Route2 0.152: v184.15,69.22 186.06,69.22 188.59,66.67 193.68,71.75 196.85,71.75 205.1,80.01 205.1,81.92 v203.84,83.19
  Bottom 0.152: v151.76,40.01 144.78,46.99 144.78,50.16 D21.H2
DAEX3-3  (via drill 0.61)
  Route2 0.152: v46.99,79.38 48.26,79.38 53.98,85.09 53.98,90.81 90.17,127 90.17,127.64 91.44,128.91 92.71,128.91 104.78,140.97 107.95,140.97 124.46,157.48 133.35,157.48 145.41,145.41 146.69,145.41 149.22,147.96 150.5,147.96 151.76,149.22 156.84,149.22 157.48,149.86 160.66,149.86 161.29,150.5 v163.19,150.5 | v206.38,107.32 207.65,106.05 208.28,106.68 208.91,106.68 209.55,107.32 209.55,109.86 208.28,111.12 213.36,116.21 215.26,116.21 215.9,116.84 220.98,111.76 222.25,113.03 224.79,113.03 231.14,106.68 229.87,105.41 C14.N2
  Route15 0.152: v163.19,150.5 164.47,150.5 166.37,148.59 166.37,146.69 205.74,107.32 v206.38,107.32
  Bottom 0.152: v46.99,79.38 48.9,77.47 48.9,73.03 50.8,71.12 50.8,70.48 57.78,63.5 58.42,63.5 60.33,61.59 66.04,61.59 67.31,60.32 68.58,60.32 77.47,51.43 80.64,51.43 D26.H2
DAEX3-4  (via drill 0.61)
  Top 0.152: v133.35,31.12 132.72,30.48 132.08,30.48 130.18,28.58 130.18,27.3 105.41,2.54 78.74,2.54 77.47,1.27 32.38,1.27 15.88,17.78 15.88,45.09 17.14,46.35 17.14,50.16 D31.H2 | v163.19,33.66 168.28,33.66 178.44,43.81 178.44,46.35 177.16,47.62 180.34,50.8 v180.97,50.8 | v196.85,61.59 200.66,65.41 202.56,65.41 204.47,63.5 205.1,63.5 215.9,74.3 217.81,74.3 226.69,83.19 226.69,86.36 220.98,92.08 226.06,97.16 229.24,97.16 229.87,97.79 C14.R2
  Route2 0.152: v133.35,31.12 135.25,31.12 138.43,27.94 143.51,33.02 148.59,33.02 149.86,34.29 151.13,34.29 153.03,36.2 156.21,36.2 160.66,31.75 162.56,33.66 v163.19,33.66 | v180.97,50.8 180.97,52.7 187.32,59.05 187.32,59.69 188.59,60.96 190.5,60.96 191.13,61.59 v196.85,61.59
DAEX3-5  (via drill 0.61)
  Top 0.152: v87,273.05 81.92,267.97 76.2,267.97 68.58,260.35 68.58,257.81 A27.H2
  Route2 0.152: v243.21,108.59 243.21,106.68 245.75,104.14 238.12,96.52 236.85,96.52 234.31,93.98 233.04,93.98 230.5,91.44 C14.T2
  Route15 0.152: v104.78,267.97 105.41,267.97 124.46,248.92 130.18,248.92 137.16,241.94 138.43,241.94 140.34,240.03 145.41,240.03 165.1,220.34 165.1,207.01 168.28,203.84 168.28,192.41 190.5,170.18 190.5,168.91 193.68,165.74 193.68,160.02 200.66,153.03 200.66,149.86 220.98,129.54 220.98,128.91 222.25,127.64 223.52,127.64 226.06,125.09 227.33,125.09 228.6,123.83 v228.6,123.19
  Bottom 0.152: v87,273.05 93.34,279.4 v104.78,267.97 | v228.6,123.19 228.6,122.56 242.57,108.59 v243.21,108.59
DAEX3-6  (via drill 0.61)
  Route2 0.152: v203.84,74.93 205.74,73.03 212.72,73.03 215.26,75.57 216.53,75.57 226.06,85.09 229.87,85.09 C14.V2
  Route15 0.152: v199.39,79.38 v203.84,74.93 | v150.5,112.4 149.86,112.4 143.51,118.75 142.88,118.75 135.89,125.73 127.64,125.73 125.73,123.83 v102.87,146.69 | v95.25,155.58 95.25,156.84 78.74,173.36 78.74,174.62 74.3,179.07 73.66,179.07 66.67,186.06 66.67,197.49 66.04,198.12 63.5,198.12 59.05,193.68 53.98,198.75 53.98,203.84 53.34,204.47 47.62,204.47 46.99,205.11 v46.35,205.11
  Bottom 0.152: v199.39,79.38 200.03,78.74 200.03,76.2 196.22,72.39 194.31,72.39 188.59,78.11 188.59,79.38 170.81,97.16 170.18,97.16 165.1,102.23 165.1,102.87 155.57,112.4 v150.5,112.4 | v102.87,146.69 102.87,149.22 97.79,154.31 96.52,154.31 v95.25,155.58 | v46.35,205.11 41.91,205.11 41.27,205.74 41.27,206.38 39.37,208.28 39.37,210.82 34.92,215.27 34.92,217.81 3.17,249.56 3.17,255.27 4.45,256.54 A32.H2
DATA_OUT  (via drill 0.61)
  Top 0.152: v22.86,142.24 26.04,142.24 v31.11,147.32 | v165.74,262.89 166.37,262.89 177.8,274.32 184.15,274.32 187.96,278.13 197.49,278.13 v202.56,283.21
  Route2 0.152: v31.11,147.32 31.75,147.32 50.8,166.37 54.61,166.37 55.24,167 57.15,167 95.25,205.11 95.25,206.38 107.95,219.08 116.2,219.08 149.86,252.73 154.94,252.73 160.66,258.44 161.29,258.44 v165.74,262.89 | v202.56,283.21 208.91,283.21 215.26,289.56 215.9,289.56 222.25,283.21 225.43,283.21 226.69,284.48 238.12,284.48 238.76,285.11 246.38,285.11 v250.82,289.56
  Route15 0.152: v270.51,279.4 271.78,279.4 276.86,274.32 282.57,274.32 307.98,248.92 307.98,246.38 309.25,245.11 A08.M2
